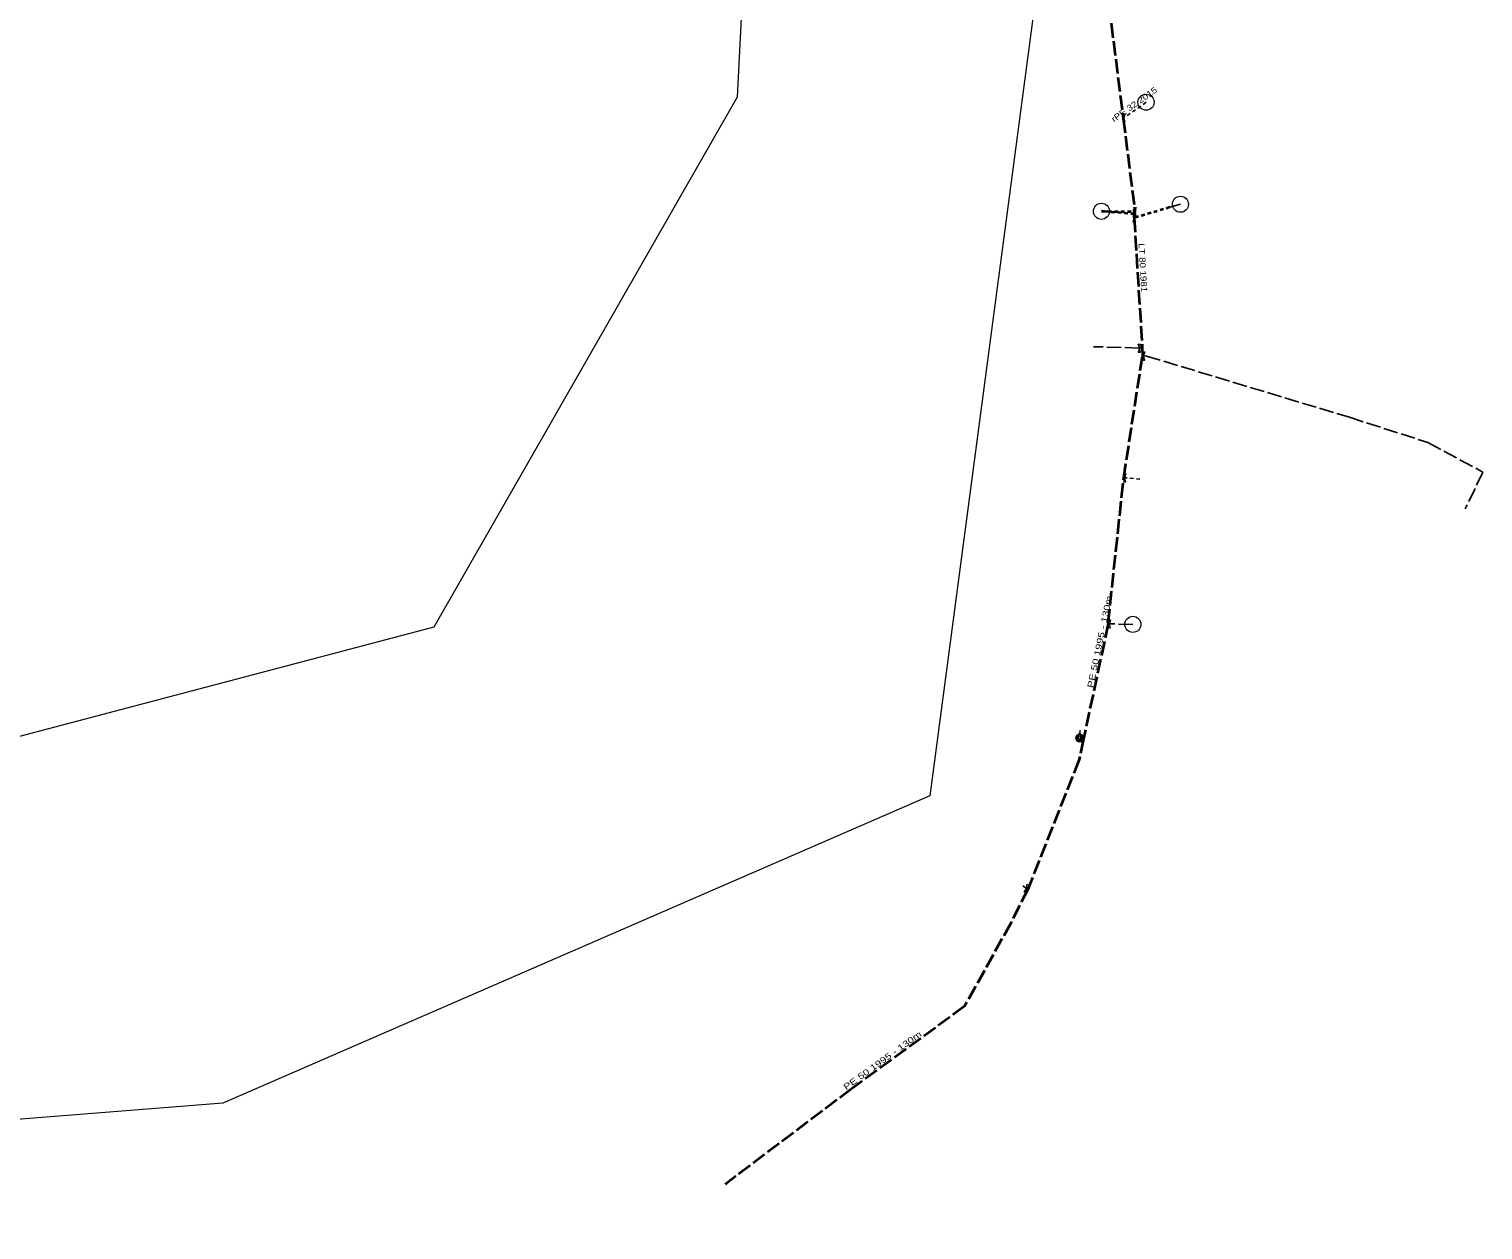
# Model space of a CAD drawing. Extents: x -616592 to -615844, y -1088988 to -1088174.
# Drawn here: x -616410.7 to -616230, y -1088988 to -1088838.7 of the extents above; entities that cross this region are included whole.
import ezdxf
from ezdxf.enums import TextEntityAlignment as Align

# ---------------------------------------------------------------- set-up
doc = ezdxf.new("R2010")
doc.units = 0
doc.header["$LTSCALE"] = 0.3
for name, pattern in [('DASH_DOUBLE_DOT', [9.2, 5, -1.2, 0.3, -1.2, 0.3, -1.2]), ('LONG_DASHED', [7.5, 6, -1.5]), ('SHORT_DASHED', [2.7, 1.5, -1.2])]:
    doc.linetypes.add(name, pattern=pattern)
for name, color, linetype, lineweight in [('1', 7, 'Continuous', 13), ('10', 7, 'Continuous', 13), ('35', 7, 'LONG_DASHED', 35), ('36', 7, 'SHORT_DASHED', 35), ('50', 7, 'LONG_DASHED', 25), ('51', 7, 'SHORT_DASHED', 25)]:
    doc.layers.add(name, color=color, linetype=linetype, lineweight=lineweight)
doc.layers.add('16', color=7, linetype='Continuous')
doc.layers.add('19', color=7, linetype='Continuous')

msp = doc.modelspace()

# ---------------------------------------------------------------- linework, layer by layer
at = {"layer": '1'}
msp.add_lwpolyline([(-616257.711, -1088587.328), (-616274.902, -1088683.788), (-616283.975, -1088822.271), (-616298.779, -1088934.012), (-616386.643, -1088972.214), (-616585.294, -1088987.972), (-616591.502, -1088951.68), (-616447.289, -1088935.922), (-616360.379, -1088913.001), (-616322.655, -1088847.102), (-616317.402, -1088743.479), (-616316.925, -1088623.142)], dxfattribs=at)
at = {"layer": '10'}
msp.add_line((-616280.115, -1088926.315), (-616280.256, -1088926.174), dxfattribs=at)
for points in [[(-616274.629, -1088849.7), (-616274.779, -1088849.2), (-616274.479, -1088849.2), (-616274.629, -1088849.7), (-616274.779, -1088850.2), (-616274.479, -1088850.2)], [(-616273.361, -1088862.127), (-616273.511, -1088861.627), (-616273.211, -1088861.627), (-616273.361, -1088862.127), (-616273.511, -1088862.627), (-616273.211, -1088862.627)], [(-616273.334, -1088861.649), (-616273.484, -1088861.149), (-616273.184, -1088861.149), (-616273.334, -1088861.649), (-616273.484, -1088862.149), (-616273.184, -1088862.149)], [(-616273.259, -1088861.334), (-616273.409, -1088860.834), (-616273.109, -1088860.834), (-616273.259, -1088861.334), (-616273.409, -1088861.834), (-616273.109, -1088861.834)], [(-616272.707, -1088878.317), (-616272.857, -1088877.817), (-616272.557, -1088877.817), (-616272.707, -1088878.317), (-616272.857, -1088878.817), (-616272.557, -1088878.817)], [(-616272.188, -1088879.306), (-616272.338, -1088878.806), (-616272.038, -1088878.806), (-616272.188, -1088879.306), (-616272.338, -1088879.806), (-616272.038, -1088879.806)], [(-616274.553, -1088894.441), (-616274.703, -1088893.941), (-616274.403, -1088893.941), (-616274.553, -1088894.441), (-616274.703, -1088894.941), (-616274.403, -1088894.941)], [(-616276.469, -1088912.608), (-616276.619, -1088912.108), (-616276.319, -1088912.108), (-616276.469, -1088912.608), (-616276.619, -1088913.108), (-616276.319, -1088913.108)], [(-616286.739, -1088945.516), (-616286.678, -1088944.998), (-616286.403, -1088945.117), (-616286.739, -1088945.516), (-616287.075, -1088945.915), (-616286.8, -1088946.034)]]:
    msp.add_lwpolyline(points, close=True, dxfattribs=at)
msp.add_lwpolyline([(-616280.115, -1088925.815), (-616280.115, -1088926.315), (-616279.974, -1088926.174)], dxfattribs=at)
for centre, radius in [((-616271.884, -1088847.756), 1), ((-616267.603, -1088860.441), 1), ((-616277.423, -1088861.315), 1), ((-616273.522, -1088912.677), 1), ((-616280.1123, -1088926.8175), 0.5), ((-616280.1123, -1088926.8175), 0.35), ((-616280.1123, -1088926.8175), 0.2)]:
    msp.add_circle(centre, radius, dxfattribs=at)
at = {"layer": '35'}
for p, q in [((-616273.361, -1088862.127), (-616273.3, -1088861.653)), ((-616273.259, -1088861.334), (-616273.3, -1088861.653)), ((-616273.361, -1088862.127), (-616272.345, -1088878.338)), ((-616272.345, -1088878.338), (-616272.323, -1088879.289))]:
    msp.add_line(p, q, dxfattribs=at)
for points in [[(-616278.755, -1088817.853), (-616274.722, -1088849.757), (-616273.259, -1088861.334)], [(-616276.589, -1088912.586), (-616274.653, -1088894.439), (-616272.323, -1088879.289)], [(-616276.589, -1088912.586), (-616279.659, -1088926.914), (-616280.209, -1088929.484), (-616286.594, -1088945.63)], [(-616286.594, -1088945.63), (-616288.701, -1088949.828), (-616294.439, -1088960.169), (-616308.522, -1088970.462), (-616323.978, -1088982.115), (-616324.2, -1088982.309)]]:
    msp.add_lwpolyline(points, dxfattribs=at)
at = {"layer": '36'}
for p, q in [((-616277.423, -1088861.315), (-616273.259, -1088861.334)), ((-616273.334, -1088861.649), (-616277.423, -1088861.315)), ((-616268.931, -1088860.821), (-616273.361, -1088862.127)), ((-616280.113, -1088926.817), (-616279.659, -1088926.914))]:
    msp.add_line(p, q, dxfattribs=at)
at = {"layer": '50'}
for p, q in [((-616272.707, -1088878.317), (-616278.414, -1088878.147)), ((-616272.345, -1088878.338), (-616272.707, -1088878.317)), ((-616272.323, -1088879.289), (-616272.188, -1088879.306)), ((-616276.469, -1088912.608), (-616276.589, -1088912.586)), ((-616273.522, -1088912.677), (-616276.469, -1088912.608)), ((-616286.739, -1088945.516), (-616287.205, -1088945.189)), ((-616286.594, -1088945.63), (-616286.739, -1088945.516))]:
    msp.add_line(p, q, dxfattribs=at)
msp.add_lwpolyline([(-616272.188, -1088879.306), (-616271.842, -1088879.311), (-616246.605, -1088886.925), (-616236.831, -1088890.065), (-616229.997, -1088893.747), (-616232.19, -1088898.307)], dxfattribs=at)
at = {"layer": '51'}
for p, q in [((-616271.884, -1088847.756), (-616274.629, -1088849.7)), ((-616274.629, -1088849.7), (-616274.722, -1088849.757)), ((-616273.3, -1088861.653), (-616273.334, -1088861.649))]:
    msp.add_line(p, q, dxfattribs=at)
at = {"layer": '51', "linetype": 'DASH_DOUBLE_DOT'}
msp.add_line((-616268.931, -1088860.821), (-616267.603, -1088860.441), dxfattribs=at)
at = {"layer": '51'}
msp.add_lwpolyline([(-616272.633, -1088894.622), (-616274.553, -1088894.441), (-616274.653, -1088894.439)], dxfattribs=at)

# ---------------------------------------------------------------- texts
at = {"layer": '16'}
for s, rotation, width, p in [('LT 80 1981', 273.363, 1.2, (-616272.6438, -1088868.349)), ('PE 50 1995 - 130m', 78.173, 1.35, (-616277.2734, -1088914.9129)), ('PE 50 1995 - 130m', 35.832, 1.35, (-616304.432, -1088967.2055))]:
    msp.add_text(s, height=0.75, rotation=rotation, dxfattribs=dict(at, width=width)).set_placement(p, align=Align.CENTER)
at = {"layer": '19', "width": 1.2}
msp.add_text('rPE 32 2015', height=0.75, rotation=35.306, dxfattribs=at).set_placement((-616273.1397, -1088848.3384), align=Align.CENTER)

doc.saveas('drawing.dxf')
